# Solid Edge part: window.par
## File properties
Title: Window
Author: Lee
Template: Iso Part.par
Last saved by: Lee
Revision: 16
Application: Solid Edge
Material: Titanium
Face Style: Steel
Fill Style: ANSI31(Iron)
Virtual Style: Silver
Coef. of Thermal Exp: 9e-06
Thermal Conductivity: 16.0
Specific Heat: 519.0
Modulus of Elasticity: 102731879300.0
Poisson's Ratio: 0.34
Yield Stress: 172368925.0
Ultimate Stress: 241316495.0
Elongation: 0.0
Manager: Garth Huber
Company: U of R Physics
Density: 4511.000 kg/m^3
Accuracy: 0.990
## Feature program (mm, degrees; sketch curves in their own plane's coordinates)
sketch for "unnamed RevolvedProtrusion 1" plane through (0, 0, 0) normal (0, -1, 0) x-axis (1, 0, 0)
  line (0, 100) -> (926.2, 100)
  line (926.2, 100) -> (926.2, -100)
  line (926.2, -100) -> (850, -100)
  arc centre (0, -2485.7059) radius 2532.6059 from (0, 46.9) to (850, -100) cw
  line (0, 100) -> (0, 46.9)
revolve "unnamed RevolvedProtrusion 1" add full turn 360 deg
thinwall "unnamed Thinwall 1"
sketch for "Hole_1" plane through (0, 0, 1.016) normal (0, 0, 1) x-axis (-1, 0, 0)
hole "Hole_1" diameter 19.05 through
sketch for "unnamed Hole 1" plane through (0, 0, 1.016) normal (0, 0, 1) x-axis (-1, 0, 0)
hole "unnamed Hole 1" through
sketch for "unnamed Hole 2" plane through (0, 0, 1.016) normal (0, 0, 1) x-axis (-1, 0, 0)
hole "unnamed Hole 2" through
sketch for "unnamed Hole 3" plane through (0, 0, 1.016) normal (0, 0, 1) x-axis (-1, 0, 0)
hole "unnamed Hole 3" through
pattern "unnamed Pattern 1" of "Hole_1", "unnamed Hole 1", "unnamed Hole 2", "unnamed Hole 3"
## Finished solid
Body 1: solid body, 9 faces, 12 edges, 0 vertices.
  Faces by surface: cylinder 5, plane 2, sphere 2
  Edges by curve: circle 12
Bounding box of the edges (mm; curved faces can reach further): 1852.400 x 1852.400 x 1.016, from (-926.2, -926.2, -100) to (926.2, 926.2, -98.984).
Cylindrical faces by radius (mm): R9.525 x4, R926.2 x1
Spherical faces by radius (mm): R2532.6059 x1, R2533.6219 x1
Planar faces by outward normal: +z 1, -z 1
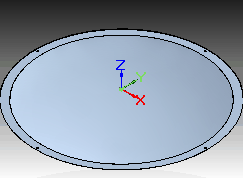
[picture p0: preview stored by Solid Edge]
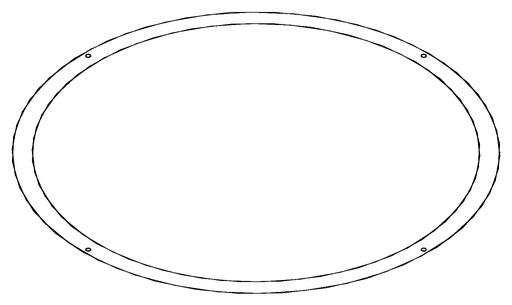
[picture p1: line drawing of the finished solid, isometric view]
